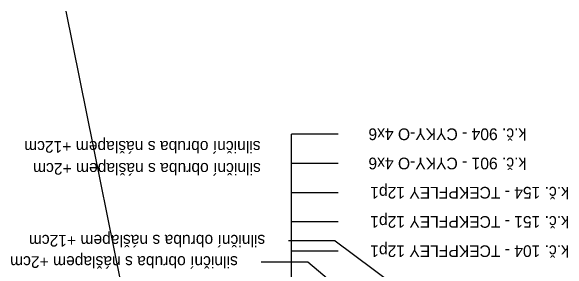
# Model space of a CAD drawing. Extents: x -728547 to -728179, y -1073068 to -1072839.
# Drawn here: x -728508.53 to -728484.68, y -1073024.51 to -1073013.44 of the extents above; entities that cross this region are included whole.
import ezdxf

# ---------------------------------------------------------------- set-up
doc = ezdxf.new("R2010")
doc.units = 0
for name, color, linetype in [('_NOR-popis', 7, 'Continuous'), ('_NOR-VDZ', 7, 'Continuous'), ('KOS_kabelová trasa popis', 7, 'Continuous')]:
    doc.layers.add(name, color=color, linetype=linetype)

msp = doc.modelspace()

# ---------------------------------------------------------------- linework, layer by layer
at = {"layer": '_NOR-popis'}
for p, q in [((-728494.648, -1073023.263), (-728496.648, -1073023.263)), ((-728494.648, -1073023.263), (-728489.823, -1073026.852)), ((-728495.822, -1073024.175), (-728497.822, -1073024.175)), ((-728491.969, -1073027.422), (-728495.822, -1073024.175))]:
    msp.add_line(p, q, dxfattribs=at)
at = {"layer": '_NOR-VDZ'}
msp.add_lwpolyline([(-728502.909, -1073029.566), (-728502.929, -1073029.468), (-728506.181, -1073013.442)], dxfattribs=at)
at = {"layer": 'KOS_kabelová trasa popis'}
for p, q in [((-728496.527, -1073024.959), (-728496.527, -1073018.709)), ((-728494.527, -1073018.709), (-728496.527, -1073018.709)), ((-728494.527, -1073019.959), (-728496.527, -1073019.959)), ((-728494.527, -1073021.209), (-728496.527, -1073021.209)), ((-728494.527, -1073022.459), (-728496.527, -1073022.459)), ((-728494.527, -1073023.709), (-728496.527, -1073023.709))]:
    msp.add_line(p, q, dxfattribs=at)

# ---------------------------------------------------------------- texts
at = {"layer": '_NOR-popis'}
for s, p in [('silniční obruba s nášlapem +12cm', (-728497.848, -1073018.997)), ('silniční obruba s nášlapem +2cm', (-728497.838, -1073019.938)), ('silniční obruba s nášlapem +12cm', (-728497.648, -1073023.013)), ('silniční obruba s nášlapem +2cm', (-728498.822, -1073023.925))]:
    msp.add_text(s, height=0.5, rotation=180, dxfattribs=at).set_placement(p)
at = {"layer": 'KOS_kabelová trasa popis'}
for s, p in [('k.č. 904 - CYKY-O 4x6', (-728486.462, -1073018.459)), ('k.č. 901 - CYKY-O 4x6', (-728486.462, -1073019.709)), ('k.č. 154 - TCEKPFLEY 12p1', (-728484.636, -1073020.959)), ('k.č. 151 - TCEKPFLEY 12p1', (-728484.636, -1073022.209)), ('k.č. 104 - TCEKPFLEY 12p1', (-728484.636, -1073023.459))]:
    msp.add_text(s, height=0.5, rotation=180, dxfattribs=at).set_placement(p)

doc.saveas('drawing.dxf')
